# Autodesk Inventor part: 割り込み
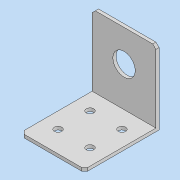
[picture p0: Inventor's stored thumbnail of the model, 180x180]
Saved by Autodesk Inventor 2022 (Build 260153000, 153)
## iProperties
Created: 2021-07
Part Number: 割り込み
Material: 一般
Document SubType Name: Modeling
Designer: DesignLab
Density: 1 g/cm^3
Appearance: 既定
Author: DesignLab
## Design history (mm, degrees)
sketch "スケッチ1"
  geometry: L1 (0, 0)-(70, 0); L2 (70, 0)-(70, 70); L3 (70, 70)-(0, 70); L4 (0, 70)-(0, 0)
  constraints: 8 end point, 2 parallel, 1 horizontal, 1 perpendicular
  dimensions: "d0" = 70 distance of L3.end L2.end; "d1" = 70 distance of L2.end L1.end
extrude "押し出し1" new body sketch "スケッチ1" taper "d3" = 0 deg; stored distance "全幅" = 60
feature "シェル1" dims "d4" = 3
sketch "スケッチ2"
  geometry: L1 (0, -70)-(60, -70) reference; 3 further points
  constraints: 1 midpoint, 1 vertical alignment
  dimensions: "d5" = 40 distance from line of point (30, -30) L1
hole "穴1" sketch "スケッチ2" at (30, -30) diameter "d6" = 21; stored, may be unused: countersink angle "d10" = 90 deg, drill point angle "d12" = 118 deg; dims "d7" = 6, "d8" = 4, "d9" = 2, "d11" = 8
sketch "スケッチ3"
  geometry: L1 (15, -47)-(45, -47); L2 (45, -47)-(45, -17); L3 (45, -17)-(15, -17); L4 (15, -17)-(15, -47); L5 (15, -47)-(45, -17); L6 (45, -47)-(15, -17); L7 (60, 3)-(0, 3) reference; 4 further points
  constraints: 12 end point, 4 midpoint, 2 parallel, 1 horizontal, 1 perpendicular, 1 vertical alignment
  dimensions: "d13" = 30 distance of L3.end L2.end (= 0.5 x 全幅); "d14" = 30 distance of L2.end L1.end; "d15" = 20 distance between parallel lines of L3 L7
hole "穴2" sketch "スケッチ3" at (15, -47), (15, -17), (45, -17), (45, -47) diameter "d16" = 7; stored, may be unused: countersink angle "d20" = 90 deg, drill point angle "d22" = 118 deg; dims "d17" = 6, "d18" = 4, "d19" = 2, "d21" = 8
chamfer "面取り1" distance "d23" = 3; stored, may be unused: second distance "d24" = 2, angle "d25" = 45 deg
node "ソリッド1"
